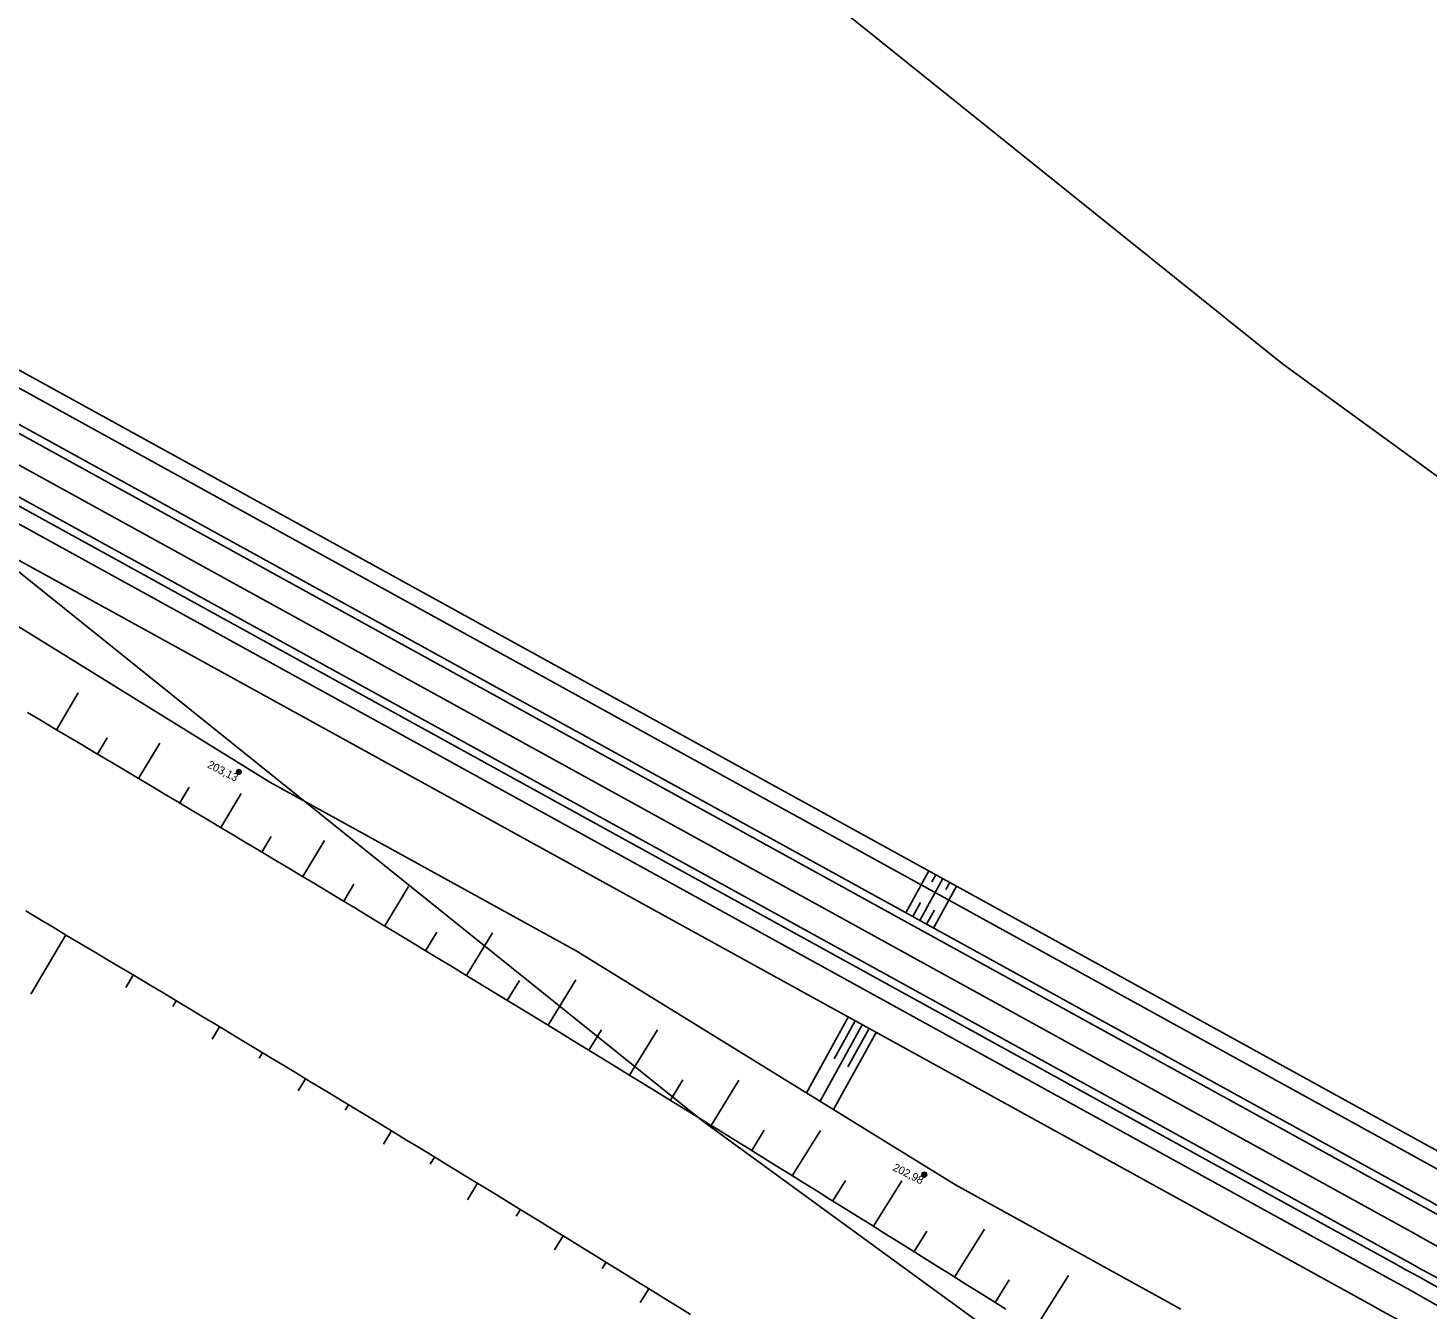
# Model space of a CAD drawing. Extents: x -551750 to -547457, y -1150683 to -1148508.
# Drawn here: x -550341 to -550252.9, y -1149039.7 to -1148959 of the extents above; entities that cross this region are included whole.
import ezdxf

# ---------------------------------------------------------------- set-up
doc = ezdxf.new("R2010")
doc.units = 0
for name, color, linetype in [('SO221815_VYSKOPIS', 7, 'Continuous'), ('u_ochranne_pasmo_CD', 7, 'Continuous'), ('u_trat navrh', 7, 'Continuous')]:
    doc.layers.add(name, color=color, linetype=linetype)

# ---------------------------------------------------------------- blocks, each defined once
blk = doc.blocks.new('SO221824_VYSKOPIS')
at = {"layer": 'SO221815_VYSKOPIS'}
for p, q in [((0.123, -0.085), (-0.123, 0.085)), ((0.086, 0.123), (-0.086, -0.123)), ((0.086, 0.123), (0, 0)), ((0, 0), (0.123, -0.085))]:
    blk.add_line(p, q, dxfattribs=at)
blk.add_lwpolyline([(-0.086, -0.123), (0, 0), (-0.123, 0.085)], dxfattribs=at)
blk.add_circle((0, 0), 0.15, dxfattribs=at)
for start, end in [(145.36204, 235.15382), (325.36204, 55.15382)]:
    blk.add_arc((0, 0), 0.15, start, end, dxfattribs=at)

msp = doc.modelspace()

# ---------------------------------------------------------------- linework, layer by layer
at = {"layer": 'u_ochranne_pasmo_CD'}
for points in [[(-551204.608, -1148514.466), (-551167.268, -1148510.525), (-551132.147, -1148508.579), (-551091.632, -1148508.39), (-551057.892, -1148509.373), (-551016.744, -1148513.627), (-550982.17, -1148519.492), (-550943.055, -1148529.955), (-550913.311, -1148538.83), (-550891.178, -1148546.582), (-550830.711, -1148571.434), (-550783.204, -1148596.843), (-550731.358, -1148628.54), (-550577.063, -1148738.919), (-550506.269, -1148793.922), (-550406.245, -1148864.296), (-550262.043, -1148980.172), (-550169.322, -1149047.694), (-550081.54, -1149120.017), (-549998.063, -1149180.267)], [(-551198.31, -1148574.135), (-551162.456, -1148570.351), (-551130.346, -1148568.572), (-551092.366, -1148568.394), (-551061.857, -1148569.283), (-551024.854, -1148573.108), (-550994.968, -1148578.178), (-550959.389, -1148587.695), (-550931.815, -1148595.923), (-550912.514, -1148602.683), (-550895.525, -1148609.665), (-550856.329, -1148625.775), (-550813.026, -1148648.936), (-550764.505, -1148678.6), (-550612.938, -1148787.027), (-550541.958, -1148842.175), (-550442.336, -1148912.265), (-550342.715, -1148992.318), (-550298.516, -1149027.836), (-550206.092, -1149095.142), (-550118.211, -1149167.545), (-550033.177, -1149228.919)]]:
    msp.add_lwpolyline(points, dxfattribs=at)
at = {"layer": 'u_trat navrh'}
for p, q in [((-550460.228, -1148921.161), (-550253.98, -1149034.784)), ((-550461.073, -1148922.694), (-550254.824, -1149036.317)), ((-550461.796, -1148924.007), (-550255.548, -1149037.631)), ((-550462.762, -1148925.759), (-550256.513, -1149039.383)), ((-550441.651, -1148926.543), (-550251.929, -1149031.062)), ((-550442.616, -1148928.295), (-550252.894, -1149032.814)), ((-550442.857, -1148928.733), (-550253.135, -1149033.252)), ((-550371.01, -1148964.318), (-550251.446, -1149030.186)), ((-550344.482, -1148994.916), (-550325.743, -1149006.495)), ((-550339.178, -1149003.199), (-550337.804, -1149000.877)), ((-550336.59, -1149004.732), (-550335.983, -1149003.71)), ((-550334.005, -1149006.269), (-550332.68, -1149004.043)), ((-550331.42, -1149007.808), (-550330.834, -1149006.826)), ((-550325.743, -1149006.495), (-550306.474, -1149017.111)), ((-550328.838, -1149009.351), (-550327.556, -1149007.209)), ((-550326.258, -1149010.897), (-550325.668, -1149009.915)), ((-550323.679, -1149012.446), (-550322.309, -1149010.168)), ((-550284.78, -1149012.964), (-550284.298, -1149012.088)), ((-550321.103, -1149013.998), (-550320.458, -1149012.929)), ((-550318.528, -1149015.553), (-550317.03, -1149013.077)), ((-550285.745, -1149014.716), (-550284.78, -1149012.964)), ((-550284.101, -1149012.767), (-550283.86, -1149012.329)), ((-550283.905, -1149013.446), (-550283.422, -1149012.57)), ((-550283.225, -1149013.25), (-550282.984, -1149012.812)), ((-550283.029, -1149013.929), (-550282.546, -1149013.053)), ((-550284.87, -1149015.198), (-550283.905, -1149013.446)), ((-550283.994, -1149015.681), (-550283.029, -1149013.929)), ((-550285.308, -1149014.957), (-550284.825, -1149014.081)), ((-550284.432, -1149015.439), (-550283.949, -1149014.563)), ((-550338.579, -1149016.114), (-550340.794, -1149019.835)), ((-550315.955, -1149017.111), (-550315.251, -1149015.95)), ((-550313.384, -1149018.672), (-550311.749, -1149015.985)), ((-550306.474, -1149017.111), (-550282.625, -1149031.848)), ((-550334.348, -1149018.64), (-550334.821, -1149019.43)), ((-550310.815, -1149020.237), (-550310.047, -1149018.978)), ((-550308.247, -1149021.804), (-550306.492, -1149018.934)), ((-550331.634, -1149020.266), (-550331.844, -1149020.617)), ((-550328.921, -1149021.896), (-550329.388, -1149022.672)), ((-550291.994, -1149026.058), (-550289.364, -1149021.285)), ((-550291.142, -1149026.584), (-550288.489, -1149021.767)), ((-550290.247, -1149023.924), (-550288.926, -1149021.526)), ((-550305.682, -1149023.375), (-550304.893, -1149022.089)), ((-550303.118, -1149024.948), (-550301.367, -1149022.1)), ((-550290.291, -1149027.111), (-550287.613, -1149022.25)), ((-550289.384, -1149024.428), (-550288.051, -1149022.008)), ((-550326.211, -1149023.529), (-550326.42, -1149023.877)), ((-550323.502, -1149025.166), (-550323.968, -1149025.937)), ((-550300.557, -1149026.525), (-550299.768, -1149025.246)), ((-550297.997, -1149028.105), (-550296.243, -1149025.267)), ((-550320.796, -1149026.806), (-550321.008, -1149027.156)), ((-550318.092, -1149028.45), (-550318.595, -1149029.278)), ((-550295.439, -1149029.688), (-550294.648, -1149028.411)), ((-550292.883, -1149031.273), (-550291.118, -1149028.433)), ((-550315.389, -1149030.097), (-550315.658, -1149030.536)), ((-550290.329, -1149032.862), (-550289.531, -1149031.582)), ((-550287.777, -1149034.454), (-550285.993, -1149031.6)), ((-550312.689, -1149031.747), (-550313.323, -1149032.782)), ((-550282.625, -1149031.848), (-550268.438, -1149039.663)), ((-550309.991, -1149033.401), (-550310.252, -1149033.826)), ((-550307.295, -1149035.059), (-550307.836, -1149035.937)), ((-550285.227, -1149036.049), (-550284.419, -1149034.76)), ((-550282.678, -1149037.648), (-550280.789, -1149034.64)), ((-550304.602, -1149036.719), (-550304.845, -1149037.114)), ((-550280.132, -1149039.249), (-550279.238, -1149037.83)), ((-550277.587, -1149040.853), (-550275.503, -1149037.552)), ((-550301.91, -1149038.383), (-550302.452, -1149039.26))]:
    msp.add_line(p, q, dxfattribs=at)
for points in [[(-550255.065, -1149036.755), (-550461.314, -1148923.131)], [(-550341.005, -1149002.119), (-550340.143, -1149002.628), (-550339.281, -1149003.138), (-550338.419, -1149003.648), (-550337.558, -1149004.158), (-550336.697, -1149004.669), (-550335.836, -1149005.18), (-550334.975, -1149005.692), (-550334.114, -1149006.203), (-550333.254, -1149006.716), (-550332.393, -1149007.228), (-550331.533, -1149007.741), (-550330.673, -1149008.254), (-550329.814, -1149008.768), (-550328.954, -1149009.282), (-550328.095, -1149009.796), (-550327.236, -1149010.31), (-550326.377, -1149010.825), (-550325.518, -1149011.34), (-550324.66, -1149011.856), (-550323.802, -1149012.372), (-550322.944, -1149012.888), (-550322.086, -1149013.405), (-550321.228, -1149013.922), (-550320.371, -1149014.439), (-550319.514, -1149014.957), (-550318.657, -1149015.475), (-550317.8, -1149015.993), (-550316.944, -1149016.512), (-550316.087, -1149017.031), (-550315.231, -1149017.55), (-550314.375, -1149018.07), (-550313.519, -1149018.59), (-550312.664, -1149019.11), (-550311.809, -1149019.631), (-550310.953, -1149020.152), (-550310.099, -1149020.673), (-550309.244, -1149021.195), (-550308.389, -1149021.717), (-550307.535, -1149022.24), (-550306.681, -1149022.762), (-550305.827, -1149023.286), (-550304.974, -1149023.809), (-550304.12, -1149024.333), (-550303.267, -1149024.857), (-550302.414, -1149025.381), (-550301.561, -1149025.906), (-550300.708, -1149026.431), (-550299.856, -1149026.957), (-550299.004, -1149027.483), (-550298.152, -1149028.009), (-550297.3, -1149028.535), (-550296.449, -1149029.062), (-550295.597, -1149029.589), (-550294.746, -1149030.117), (-550293.895, -1149030.645), (-550293.044, -1149031.173), (-550292.194, -1149031.702), (-550291.344, -1149032.231), (-550290.494, -1149032.76), (-550289.644, -1149033.289), (-550288.794, -1149033.819), (-550287.945, -1149034.35), (-550287.095, -1149034.88), (-550286.246, -1149035.411), (-550285.398, -1149035.942), (-550284.549, -1149036.474), (-550283.701, -1149037.006), (-550282.852, -1149037.538), (-550282.004, -1149038.071), (-550281.157, -1149038.604), (-550280.309, -1149039.137), (-550279.462, -1149039.671)], [(-550341.108, -1149014.61), (-550340.249, -1149015.12), (-550339.391, -1149015.631), (-550338.533, -1149016.142), (-550337.675, -1149016.653), (-550336.817, -1149017.165), (-550335.96, -1149017.676), (-550335.102, -1149018.189), (-550334.245, -1149018.701), (-550333.388, -1149019.214), (-550332.532, -1149019.728), (-550331.675, -1149020.241), (-550330.819, -1149020.755), (-550329.963, -1149021.27), (-550329.107, -1149021.784), (-550328.251, -1149022.299), (-550327.396, -1149022.815), (-550326.54, -1149023.33), (-550325.685, -1149023.846), (-550324.83, -1149024.363), (-550323.976, -1149024.88), (-550323.121, -1149025.397), (-550322.267, -1149025.914), (-550321.413, -1149026.432), (-550320.559, -1149026.95), (-550319.706, -1149027.468), (-550318.852, -1149027.987), (-550317.999, -1149028.506), (-550317.146, -1149029.026), (-550316.293, -1149029.545), (-550315.441, -1149030.066), (-550314.588, -1149030.586), (-550313.736, -1149031.107), (-550312.884, -1149031.628), (-550312.032, -1149032.15), (-550311.181, -1149032.671), (-550310.33, -1149033.194), (-550309.478, -1149033.716), (-550308.627, -1149034.239), (-550307.777, -1149034.762), (-550306.926, -1149035.286), (-550306.076, -1149035.81), (-550305.226, -1149036.334), (-550304.376, -1149036.858), (-550303.526, -1149037.383), (-550302.677, -1149037.909), (-550301.828, -1149038.434), (-550300.979, -1149038.96), (-550300.13, -1149039.486), (-550299.281, -1149040.013)]]:
    msp.add_lwpolyline(points, dxfattribs=at)
for radius, start in [(501.75, 59.58162), (502.25, 59.58162), (500, 54.5401), (497.75, 54.5401), (498.25, 54.5401), (496.75, 54.5401), (494.75, 54.5401)]:
    msp.add_arc((-550495.243, -1149472.725), radius, start, 61.14938, dxfattribs=at)

# ---------------------------------------------------------------- block references
at = {"layer": 'u_trat navrh', "rotation": -31.851985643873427}
for p in [(-550327.696, -1149005.853), (-550284.577, -1149031.205)]:
    msp.add_blockref('SO221824_VYSKOPIS', p, dxfattribs=at)

# ---------------------------------------------------------------- texts
at = {"layer": 'u_trat navrh'}
for s, p in [('203,13', (-550329.731, -1149005.558)), ('202,98', (-550286.612, -1149030.91))]:
    msp.add_text(s, height=0.5, rotation=333.25678, dxfattribs=at).set_placement(p)

doc.saveas('drawing.dxf')
